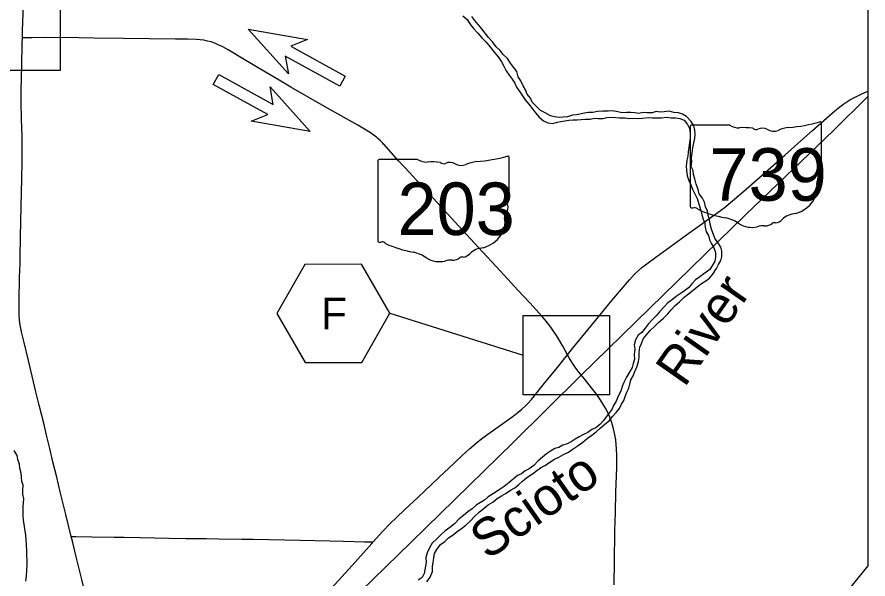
# Model space of a CAD drawing. Extents: x 0 to 680, y 0 to 440.
# Drawn here: x 391.8 to 466.9, y 290.1 to 339.7 of the extents above; entities that cross this region are included whole.
import ezdxf

# ---------------------------------------------------------------- set-up
doc = ezdxf.new("R2010")
doc.units = 0
for name, color, linetype in [('GM_X_County_Road', 7, 'Continuous'), ('GM_X_Major_River', 7, 'Continuous'), ('GM_X_Major_River_Text', 7, 'Continuous'), ('GM_X_State_Location', 7, 'Continuous'), ('GM_X_State_Route', 7, 'Continuous'), ('GM_X_State_Shield', 7, 'Continuous'), ('GM_X_Township_Road', 7, 'Continuous'), ('PM_P_Cells', 7, 'Continuous'), ('RD_X_RR_2', 7, 'Continuous'), ('SH_Border', 7, 'Continuous'), ('SH_Text', 7, 'Continuous')]:
    doc.layers.add(name, color=color, linetype=linetype)

msp = doc.modelspace()

# ---------------------------------------------------------------- linework, layer by layer
at = {"layer": 'GM_X_County_Road'}
for points in [[(392.242, 337.911), (392.245, 338.557), (392.325, 340.818)], [(392.21, 329.152), (392.165, 330.742), (392.135, 332.164), (392.142, 333.259), (392.184, 335.446), (392.223, 337.414), (392.242, 337.911)], [(396.556, 293.857), (396.079, 295.798), (395.586, 297.816), (395.273, 299.091), (394.939, 300.472), (394.657, 301.642), (394.377, 302.811), (394.12, 303.874), (393.726, 305.466), (393.442, 306.635), (392.785, 309.402), (392.399, 310.996), (392.161, 311.951), (392.067, 312.38), (392.011, 312.704), (391.972, 313.032), (391.954, 313.361), (391.951, 314.019), (391.97, 315.33), (391.972, 316.096), (391.99, 316.753), (392.04, 317.952), (392.052, 318.499), (392.078, 320.357), (392.155, 324.294), (392.182, 325.387), (392.209, 327.027), (392.223, 328.229), (392.214, 328.994), (392.21, 329.152)], [(401.963, 273.829), (401.467, 275.508), (400.44, 279.081), (399.382, 282.759), (398.878, 284.549), (398.572, 285.713), (398.118, 287.516), (397.49, 290.064), (396.993, 292.082), (396.653, 293.462), (396.556, 293.857)]]:
    msp.add_lwpolyline(points, dxfattribs=at)
at = {"layer": 'GM_X_Major_River'}
for points in [[(431.148, 339.853), (431.528, 339.513), (431.762, 339.149), (432.088, 338.73), (432.453, 338.323), (432.819, 337.903), (433.212, 337.509), (433.499, 337.157), (433.929, 336.616), (434.255, 336.21), (434.554, 335.778), (434.774, 335.387), (434.967, 334.996), (435.227, 334.592), (435.501, 334.253), (435.734, 333.902), (435.875, 333.553), (436.174, 333.134), (436.408, 332.783), (436.655, 332.418), (436.968, 332.039), (437.294, 331.62), (437.554, 331.268), (437.881, 330.902), (438.261, 330.575), (438.658, 330.408), (439.083, 330.348), (439.47, 330.448), (439.804, 330.509)], [(443.985, 331.438), (443.518, 331.419), (443.026, 331.388), (442.612, 331.301), (442.239, 331.308), (441.892, 331.247), (441.184, 331.099), (440.811, 331.065), (440.383, 330.913), (440.01, 330.906), (439.637, 330.872), (439.225, 330.919), (438.881, 331.019), (438.419, 331.28), (438.01, 331.487), (437.657, 331.827), (437.277, 332.221), (437.123, 332.57), (436.836, 332.936), (436.669, 333.299), (436.463, 333.676), (436.257, 334.107), (436.037, 334.471), (435.911, 334.913), (435.624, 335.305), (435.364, 335.67), (435.078, 336.075), (434.711, 336.442), (434.451, 336.794), (434.084, 337.107), (433.772, 337.553), (433.419, 337.933), (433.106, 338.325), (432.806, 338.69), (432.506, 339.069), (432.205, 339.421), (431.932, 339.787)], [(439.18, 300.652), (439.623, 300.885), (440.039, 301.104), (440.468, 301.324), (440.885, 301.61), (441.329, 301.896), (441.734, 302.21), (442.152, 302.549), (442.529, 302.823), (442.919, 303.11), (443.258, 303.438), (443.676, 303.778), (444.054, 304.092), (444.366, 304.473), (444.705, 304.841), (444.976, 305.183), (445.142, 305.541), (445.361, 305.884), (445.473, 306.242), (445.625, 306.6), (445.791, 306.971), (445.877, 307.33), (445.989, 307.688), (446.195, 308.058), (446.334, 308.443), (446.528, 308.893), (446.655, 309.318), (446.714, 309.678), (446.721, 310.118), (446.782, 310.571), (446.921, 310.915), (447.074, 311.326), (447.359, 311.682), (447.698, 312.05), (448.077, 312.417), (448.442, 312.797), (448.86, 313.151), (449.239, 313.531), (449.551, 313.873), (449.89, 314.254), (450.281, 314.581), (450.674, 315.014), (451.078, 315.288), (451.496, 315.614), (451.834, 315.915), (452.211, 316.216), (452.588, 316.45), (452.924, 316.684), (453.223, 317.039), (453.537, 317.528), (453.729, 317.898), (453.921, 318.242), (454.007, 318.587), (454.015, 319.068), (453.927, 319.416), (453.654, 319.821), (453.408, 320.212), (453.102, 320.992), (452.976, 321.434), (452.929, 321.849), (452.815, 322.198), (452.755, 322.599), (452.562, 322.989), (452.475, 323.378), (452.295, 323.728), (452.022, 324.12), (451.922, 324.508), (451.743, 324.965), (451.618, 325.448), (451.504, 325.824), (451.47, 326.198), (451.303, 326.548), (451.35, 326.961), (451.329, 327.295), (451.389, 327.707), (451.463, 328.173), (451.55, 328.625), (451.623, 329.025), (451.669, 329.384), (451.635, 329.745), (451.535, 330.134), (451.315, 330.525), (450.897, 330.959), (450.554, 331.165), (450.183, 331.278), (449.785, 331.312), (449.36, 331.412), (448.907, 331.38), (448.561, 331.346), (448.216, 331.392), (447.854, 331.278), (447.415, 331.272), (447.056, 331.305), (446.683, 331.232), (446.337, 331.278), (445.978, 331.297), (445.632, 331.303), (445.22, 331.283), (444.822, 331.357), (444.371, 331.445), (443.985, 331.438)], [(439.804, 330.509), (440.138, 330.583), (440.512, 330.644), (440.884, 330.651), (441.244, 330.671), (441.604, 330.692), (441.977, 330.725), (442.376, 330.732), (442.776, 330.805), (443.122, 330.772), (443.494, 330.766), (443.855, 330.853), (444.255, 330.9), (444.627, 330.88), (444.973, 330.834), (445.465, 330.825), (445.877, 330.778), (446.29, 330.798), (446.662, 330.778), (447.008, 330.799), (447.502, 330.857), (447.847, 330.824), (448.286, 330.83), (448.686, 330.85), (449.125, 330.883), (449.537, 330.835), (449.936, 330.829), (450.308, 330.769), (450.678, 330.616), (450.991, 330.237), (451.159, 329.9), (451.205, 329.486), (451.211, 329.032), (451.165, 328.659), (451.104, 328.206), (451.044, 327.807), (450.999, 327.46), (450.926, 327.088), (450.865, 326.582), (450.885, 326.208), (450.943, 325.7), (451.11, 325.297), (451.29, 324.906), (451.416, 324.531), (451.648, 324.059), (451.829, 323.709), (452.031, 323.039), (452.158, 322.663), (452.244, 322.274), (452.371, 321.885), (452.511, 321.509), (452.546, 321.175), (452.619, 320.773), (452.84, 320.436), (452.913, 320.074), (453.107, 319.71), (453.314, 319.36), (453.467, 318.93), (453.46, 318.53), (453.388, 318.171), (453.196, 317.827), (452.963, 317.444), (452.412, 317.067), (452.061, 316.806), (451.697, 316.518), (451.359, 316.19), (451.074, 315.822), (450.71, 315.561), (450.32, 315.287), (449.983, 315.053), (449.646, 314.805), (449.255, 314.505), (448.917, 314.15), (448.51, 313.704), (448.225, 313.348), (447.86, 312.994), (447.521, 312.613), (447.249, 312.271), (446.963, 311.875), (446.613, 311.641), (446.393, 311.218), (446.28, 310.793), (446.327, 310.432), (446.266, 309.952), (446.299, 309.511), (446.186, 309.139), (446.101, 308.794), (445.895, 308.451), (445.594, 307.935), (445.36, 307.472), (445.221, 307.101), (445.081, 306.703), (444.861, 306.266), (444.667, 305.803), (444.435, 305.433), (444.296, 305.088), (443.983, 304.68), (443.589, 304.14), (443.25, 303.758), (442.899, 303.457), (442.524, 303.304)], [(442.524, 303.304), (442.173, 303.056), (441.811, 302.862), (441.409, 302.669), (441.072, 302.448), (440.696, 302.214), (440.361, 302.06), (439.986, 301.933), (439.61, 301.726), (439.262, 301.625), (438.886, 301.404), (438.522, 301.157), (438.172, 300.883), (437.807, 300.555), (437.401, 300.149), (436.997, 299.849), (436.648, 299.654), (436.311, 299.393), (435.962, 299.239), (435.598, 298.925), (435.22, 298.625), (434.802, 298.285), (434.439, 298.038), (433.834, 297.674), (433.39, 297.375), (433.039, 297.074), (432.703, 296.866), (432.313, 296.619), (431.975, 296.318), (431.585, 296.058), (431.207, 295.718), (430.829, 295.417), (430.41, 294.997), (429.992, 294.671), (429.587, 294.357), (429.196, 294.004), (428.857, 293.649), (428.425, 293.283), (428.205, 292.86), (427.985, 292.41), (427.885, 292.011), (427.892, 291.584), (427.833, 291.238), (427.716, 290.6), (427.537, 290.256), (427.187, 290.021)], [(392.547, 289.936), (392.608, 290.402), (392.642, 290.855), (392.664, 291.362), (392.67, 291.735), (392.623, 292.15), (392.63, 292.55), (392.614, 293.217), (392.567, 293.578), (392.534, 293.993), (392.45, 294.541), (392.404, 294.956), (392.343, 295.29), (392.297, 295.758), (392.316, 296.105), (392.296, 296.479), (392.361, 297.198), (392.288, 297.6), (392.28, 297.961), (392.301, 298.387), (392.2, 298.736), (392.166, 299.124), (392.132, 299.471), (392.02, 299.9), (391.999, 300.247), (391.846, 300.677), (391.772, 301.025), (391.5, 301.457)], [(427.97, 289.861), (428.256, 290.283), (428.45, 290.774), (428.471, 291.2), (428.517, 291.6), (428.576, 291.959), (428.623, 292.359), (428.829, 292.729), (429.155, 293.164), (429.546, 293.437), (429.883, 293.739), (430.274, 294.025), (430.651, 294.299), (431.028, 294.56), (431.392, 294.874), (431.811, 295.24), (432.177, 295.621), (432.609, 296.04), (433.027, 296.367), (433.378, 296.668), (433.781, 296.901), (434.159, 297.215), (434.562, 297.462), (434.965, 297.682), (435.356, 297.955), (435.732, 298.149), (436.083, 298.463), (436.42, 298.751), (436.785, 299.065), (437.282, 299.39), (437.673, 299.704), (438.01, 299.925), (438.373, 300.145), (438.789, 300.392), (439.18, 300.652)]]:
    msp.add_lwpolyline(points, dxfattribs=at)
at = {"layer": 'GM_X_State_Route'}
msp.add_line((424.699, 313.579), (436.482, 309.87), dxfattribs=at)
for points in [[(392.242, 337.911), (392.245, 338.557), (392.325, 340.818)], [(424.134, 328.523), (424.076, 328.588), (423.848, 328.823), (423.642, 329.019), (423.48, 329.152), (423.343, 329.252), (423.075, 329.444), (422.612, 329.737), (421.857, 330.183), (420.139, 331.146), (418.71, 331.952), (415.963, 333.54), (414.926, 334.15), (413.701, 334.873), (411.815, 335.982), (410.408, 336.828), (409.929, 337.095), (409.536, 337.291), (409.233, 337.422), (408.921, 337.533), (408.603, 337.62), (408.279, 337.685), (407.951, 337.73), (407.623, 337.756), (406.856, 337.78), (405.761, 337.789), (401.166, 337.828), (398.541, 337.873), (397.228, 337.888), (394.274, 337.919), (393.07, 337.914), (392.242, 337.911)], [(460.129, 328.035), (460.726, 328.56), (462.034, 329.723), (463.262, 330.811), (464.003, 331.46), (464.427, 331.808), (464.778, 332.072), (465.051, 332.257), (465.332, 332.429), (465.719, 332.636), (466.315, 332.915), (466.921, 333.178)], [(440.369, 309.909), (439.959, 310.686), (439.688, 311.161), (439.403, 311.629), (439.16, 311.994), (438.903, 312.349), (438.5, 312.868), (438.338, 313.064), (438.147, 313.287), (437.638, 313.86), (437.044, 314.503), (435.999, 315.621), (435.109, 316.587), (434.072, 317.713), (432.884, 319), (430.439, 321.657), (428.884, 323.348), (428.138, 324.149), (427.322, 325.032), (426.433, 325.999), (425.467, 327.042), (424.154, 328.501), (424.134, 328.523)], [(440.369, 309.909), (440.825, 310.479), (443.117, 313.269), (444.309, 314.696), (445.151, 315.703), (445.865, 316.533), (446.309, 317.018), (446.62, 317.328), (446.95, 317.618), (447.382, 317.956), (448.174, 318.541), (451.107, 320.648), (453.686, 322.494), (454.207, 322.891), (454.968, 323.514), (455.965, 324.367), (457.364, 325.592), (459.576, 327.549), (460.129, 328.035)], [(418.545, 288.21), (420.456, 290.316), (421.629, 291.614), (423.09, 293.243), (423.218, 293.383), (424.049, 294.294), (424.726, 295.01), (425.271, 295.549), (425.989, 296.224), (427.187, 297.343), (427.744, 297.869), (429.015, 299.072), (430.364, 300.351), (431.082, 301.025), (431.733, 301.611), (432.317, 302.107), (432.829, 302.519), (433.357, 302.911), (434.966, 304.047), (435.585, 304.496), (436.015, 304.832), (436.349, 305.113), (436.671, 305.407), (436.901, 305.638), (437.19, 305.963), (438.359, 307.409), (439.457, 308.772), (440.369, 309.909)], [(442.188, 307.395), (441.876, 307.78), (441.398, 308.377), (441.075, 308.816), (440.769, 309.267), (440.538, 309.637), (440.369, 309.909)], [(444.704, 299.185), (444.728, 299.996), (444.739, 300.982), (444.721, 301.64), (444.696, 301.968), (444.645, 302.404), (444.573, 302.837), (444.482, 303.267), (444.369, 303.691), (444.269, 304.005), (444.115, 304.417), (443.938, 304.819), (443.737, 305.21), (443.518, 305.59), (443.282, 305.96), (442.966, 306.409), (442.633, 306.844), (442.188, 307.395)], [(444.501, 289.609), (444.529, 291.687), (444.542, 292.562), (444.554, 293.327), (444.576, 294.42), (444.608, 295.951), (444.662, 297.809), (444.704, 299.185)]]:
    msp.add_lwpolyline(points, dxfattribs=at)
msp.add_lwpolyline([(422.185, 317.901), (417.185, 317.885), (414.699, 313.548), (417.212, 309.225), (422.212, 309.241), (424.699, 313.579)], close=True, dxfattribs=at)
at = {"layer": 'GM_X_State_Shield'}
for p, q in [((451.219, 330.059), (451.219, 323.015)), ((454.731, 330.181), (451.333, 330.181)), ((462.82, 326.67), (462.82, 330.355)), ((423.631, 327.033), (423.631, 319.988)), ((427.143, 327.154), (423.745, 327.154)), ((435.232, 323.643), (435.232, 327.328)), ((462.819, 326.671), (462.82, 326.67)), ((435.231, 323.644), (435.232, 323.643))]:
    msp.add_line(p, q, dxfattribs=at)
for centre, major_axis, start_param, end_param in [((451.352, 330.074), (0.134, 0), 1.712693, 3.28349), ((455.54, 330.998), (1.304, 0), 4.042523, 4.731795), ((455.972, 326.226), (4.68, 0), 1.404758, 1.657858), ((457.586, 329.297), (0.782, 0), 0.950623, 2.079405), ((460.257, 328.029), (2.475, 0), 1.699011, 2.107814), ((458.688, 339.784), (12.303, 0), 4.814394, 5.042369), ((462.691, 330.371), (0.129, 0), 6.141152, 7.989035), ((457.034, 330.111), (0.376, 0), 3.836095, 5.185415), ((458.596, 330.414), (0.941, 0), 4.081561, 5.145723), ((423.764, 327.048), (0.134, 0), 1.712693, 3.28349), ((427.952, 327.972), (1.304, 0), 4.042523, 4.731795), ((428.384, 323.199), (4.68, 0), 1.404758, 1.657858), ((429.998, 326.27), (0.782, 0), 0.950623, 2.079405), ((432.669, 325.002), (2.475, 0), 1.699011, 2.107814), ((431.1, 336.757), (12.303, 0), 4.814394, 5.042369), ((435.104, 327.344), (0.129, 0), 6.141152, 7.989035), ((429.446, 327.084), (0.376, 0), 3.836095, 5.185415), ((431.008, 327.387), (0.941, 0), 4.081561, 5.145723), ((462.79, 326.4), (0.2, 0), 1.883978, 3.671073), ((461.519, 325.934), (1.2, 0), 5.934695, 6.695948), ((462.682, 326.656), (0.138, 0), 5.05454, 6.418171), ((463.283, 325.128), (0.873, 0), 2.387724, 3.262537), ((459.377, 324.659), (3.077, 0), 5.101752, 6.440018), ((435.202, 323.373), (0.2, 0), 1.883978, 3.671073), ((433.931, 322.907), (1.2, 0), 5.934695, 6.695948), ((435.094, 323.629), (0.138, 0), 5.05454, 6.418171), ((435.695, 322.101), (0.873, 0), 2.387724, 3.262537), ((451.353, 323), (0.136, 0), 3.00124, 4.508301), ((451.373, 323.721), (1.035, 0), 4.665946, 4.897461), ((451.585, 322.609), (0.373, 0), 0.519207, 1.627899), ((456.296, 328.938), (8.885, 0), 4.195997, 4.488961), ((431.789, 321.633), (3.077, 0), 5.101752, 6.440018), ((453.647, 319.851), (2.78, 0), 0.823519, 1.323587), ((458.539, 322.333), (0.994, 0), 4.937069, 5.64225), ((460.674, 321.038), (1.685, 0), 1.647645, 2.488434), ((456.654, 322.574), (1.764, 0), 4.026481, 4.996735), ((457.673, 320.138), (1.449, 0), 1.495662, 1.94098), ((457.802, 322.046), (0.94, 0), 4.691044, 5.507374), ((458.652, 321.364), (0.265, 0), 1.147584, 2.315152), ((423.765, 319.973), (0.136, 0), 3.00124, 4.508301), ((423.786, 320.694), (1.035, 0), 4.665946, 4.897461), ((423.997, 319.582), (0.373, 0), 0.519207, 1.627899), ((428.708, 325.911), (8.885, 0), 4.195997, 4.488961), ((426.059, 316.824), (2.78, 0), 0.823519, 1.323587), ((430.951, 319.306), (0.994, 0), 4.937069, 5.64225), ((433.086, 318.011), (1.685, 0), 1.647645, 2.488434), ((429.066, 319.547), (1.764, 0), 4.026481, 4.996735), ((430.085, 317.112), (1.449, 0), 1.495662, 1.94098), ((430.214, 319.019), (0.94, 0), 4.691044, 5.507374), ((431.064, 318.337), (0.265, 0), 1.147584, 2.315152)]:
    msp.add_ellipse(centre, major_axis=major_axis, ratio=0.8, start_param=start_param, end_param=end_param, dxfattribs=at)
at = {"layer": 'GM_X_Township_Road'}
msp.add_lwpolyline([(396.556, 293.857), (396.738, 293.863), (396.957, 293.87), (398.38, 293.85), (400.351, 293.809), (401.227, 293.796), (402.65, 293.775), (405.168, 293.718), (406.701, 293.687), (408.46, 293.677), (409.555, 293.664), (411.629, 293.644), (412.614, 293.626), (416.776, 293.538), (419.404, 293.484), (420.608, 293.454), (422.469, 293.407), (422.907, 293.393), (423.218, 293.383)], dxfattribs=at)
at = {"layer": 'PM_P_Cells'}
for p, q in [((412.191, 338.658), (412.191, 338.658)), ((412.191, 338.658), (417.408, 337.767)), ((415.734, 334.726), (412.191, 338.658)), ((417.408, 337.767), (415.936, 337.167)), ((415.936, 337.167), (420.754, 334.514)), ((420.272, 333.638), (415.454, 336.291)), ((415.454, 336.291), (415.734, 334.726)), ((409.098, 333.786), (409.58, 334.662)), ((409.58, 334.662), (414.398, 332.009)), ((420.754, 334.514), (420.272, 333.638)), ((413.916, 331.133), (409.098, 333.786)), ((409.339, 334.224), (409.339, 334.224)), ((420.513, 334.076), (420.513, 334.076)), ((414.398, 332.009), (414.118, 333.574)), ((414.118, 333.574), (417.661, 329.642)), ((412.444, 330.533), (413.916, 331.133)), ((417.661, 329.642), (412.444, 330.533)), ((417.661, 329.642), (417.661, 329.642))]:
    msp.add_line(p, q, dxfattribs=at)
at = {"layer": 'RD_X_RR_2'}
msp.add_lwpolyline([(365.587, 215.989), (372.377, 226.622), (380.238, 238.84), (389.713, 253.215), (394.045, 260.328), (395.778, 262.864), (396.554, 263.768), (397.211, 264.649), (398.057, 265.641), (400.091, 267.7), (402.496, 269.941), (406.01, 273.466), (412.053, 279.303), (417.596, 284.611), (426.566, 293.352), (435.599, 302.168), (441.572, 308.078), (456.142, 322.286), (463.879, 329.729), (466.921, 332.716)], dxfattribs=at)
at = {"layer": 'SH_Border'}
for points in [[(387.956, 342.014), (395.581, 342.014), (395.581, 335.014), (387.956, 335.014)], [(436.482, 313.37), (444.107, 313.37), (444.107, 306.37), (436.482, 306.37)]]:
    msp.add_lwpolyline(points, close=True, dxfattribs=at)
at = {"layer": 'SH_Text'}
msp.add_lwpolyline([(30, 430), (466.921, 430), (466.921, 291.274), (342.899, 138.716), (30, 138.716)], close=True, dxfattribs=at)

# ---------------------------------------------------------------- texts
at = {"layer": 'GM_X_Major_River_Text'}
for s, height, rotation, p in [('River', 3.3341, 55.02275, (450.702, 306.945)), ('Scioto', 3.334, 35.02295, (433.322, 291.728))]:
    msp.add_text(s, height=height, rotation=rotation, dxfattribs=at).set_placement(p)
at = {"layer": 'GM_X_State_Location'}
msp.add_text('203', height=0.00667, rotation=0.00001, dxfattribs=at).set_placement((434.725, 313.618))
for s in ['s', 'r']:
    msp.add_text(s, height=0.00667, dxfattribs=at).set_placement((437.079, 314.103))
at = {"layer": 'GM_X_State_Route'}
msp.add_text('F', height=2.8, dxfattribs=at).set_placement((418.616, 312.163))
at = {"layer": 'GM_X_State_Shield'}
for s, p in [('739', (452.925, 323.512)), ('203', (425.372, 320.485))]:
    msp.add_text(s, height=4.6406, dxfattribs=at).set_placement(p)

doc.saveas('drawing.dxf')
